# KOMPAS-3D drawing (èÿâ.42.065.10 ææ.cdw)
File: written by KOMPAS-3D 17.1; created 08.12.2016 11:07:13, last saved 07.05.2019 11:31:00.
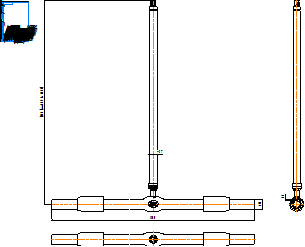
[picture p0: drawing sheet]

Sheet 1: A4, portrait

Title block, sheet 1: name: КШГ.42.065.10 СС; material: Внимание! Данный продукт является объектом авторского права ООО «Торговый Дом АДЛ». / Запрещается изменение, копирование, распространение / (в том числе путем копирования на другие сайты и ресурсы в Интернете) / или любое иное использование информации и объектов без предварительного / согласия правообладателя (ООО «Торговый Дом АДЛ»).; sheets: 1; organisation: ООО "Торговый дом АДЛ"; sheet format: A4; stored path: C:\Users\kka\KOMPAS_Work\Модели кранов для исследований\DN65\С удлинением\КШГ.35.050.25 СС ГЧ _ Шаровой кран БИВАЛ Ду50 Ру2,5 МПа полнопроходной под приварку, c удлинением штока H=950 Габаритный чертеж Lстр600.cdw; drawn by: Климкович К.А.; drawn by, date: 07.12.16

Views: Вид 1, Проекционный вид 2
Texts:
  Klimkovich
  ADL
  (от 287 до 5000)
Dimensions and other numbers on the sheet: 1500; 57; 75; 6,8; 1:1; 1; 07.12.16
